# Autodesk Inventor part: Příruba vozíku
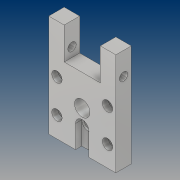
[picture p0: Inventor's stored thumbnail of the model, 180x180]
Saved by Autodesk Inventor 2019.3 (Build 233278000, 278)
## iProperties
Created: 2019-01
Part Number: Příruba vozíku
Material: Hliník 6061-AHC
Document SubType Name: Modeling
Designer: B-hon
Density: 2.7 g/cm^3
Appearance: Hliník – tmavý
Author: B-hon
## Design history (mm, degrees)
sketch "Náčrt1"
  geometry: L1 (-24.5, 16)-(24.5, 16); L2 (24.5, 16)-(24.5, -16); L3 (24.5, -16)-(-24.5, -16); L4 (-24.5, -16)-(-24.5, 16); L5 (-24.5, 16)-(24.5, -16); L6 (24.5, 16)-(-24.5, -16); L7 (32.5, -24)-(-32.5, -24); L8 (-32.5, -24)-(-32.5, 56); L9 (32.5, 56)-(32.5, -24); L10 (-32.5, 56)-(32.5, 56); 1 further point
  constraints: 20 end point, 3 horizontal, 3 parallel, 2 midpoint, 2 perpendicular
  dimensions: "d0" = 49 distance of L2.end L3.end; "d1" = 32 distance of L1.end L2.end; "d4" = 80 distance between parallel lines of L7 L10; "d21" = 8 distance between parallel lines of L9 L2; "d22" = 8 distance between parallel lines of L4 L8; "d23" = 8 distance between parallel lines of L7 L3
extrude "Vysunutí1" new body sketch "Náčrt1" distance "d5" = 12; taper "d6" = 0 deg
sketch "Náčrt2"
  geometry: L1 (0, 80)-(0, 0) reference; L2 (0, 0)-(-12, 0) reference; 2 further points
  dimensions: "d7" = 4.5 distance from line of L1 point (-4.5, 65); "d8" = 65 distance from line of L2 point (-4.5, 65)
hole "Díra1" sketch "Náčrt2" at (-4.5, 65) diameter "d9" = 8; stored, may be unused: countersink angle "d13" = 90 deg, drill point angle "d15" = 118 deg; dims "d10" = 6, "d11" = 4, "d12" = 2, "d14" = 8
sketch "Náčrt3"
  geometry: L1 (32.5, 56)-(-32.5, 56) reference; L2 (-17.5, 56)-(17.5, 56); L3 (17.5, 56)-(17.5, 32); L4 (17.5, 32)-(-17.5, 32); L5 (-17.5, 32)-(-17.5, 56); L6 (-32.5, -24)-(32.5, -24) reference; 1 further point
  constraints: 8 end point, 2 parallel, 1 horizontal, 1 perpendicular, 1 point on line
  dimensions: "d16" = 56 distance between parallel lines of L4 L6; "d17" = 35 distance of L3.end L4.end; "d18" = 15 distance from line of L1.end L5
extrude "Vysunutí2" cut sketch "Náčrt3" distance "d19" = 12; taper "d20" = 0 deg
sketch "Náčrt5"
  geometry: L1 (-24.5, 16)-(24.5, 16); L2 (24.5, 16)-(24.5, -16); L3 (24.5, -16)-(-24.5, -16); L4 (-24.5, -16)-(-24.5, 16); L5 (-24.5, 16)-(24.5, -16); L6 (24.5, 16)-(-24.5, -16); 5 further points
  constraints: 12 end point, 4 coincident, 2 midpoint, 2 parallel, 1 horizontal, 1 perpendicular
  dimensions: "d24" = 49 distance of L2.end L3.end; "d25" = 32 distance of L1.end L2.end
hole "Díra2" sketch "Náčrt5" at (-24.5, 16), (24.5, 16), (24.5, -16), (-24.5, -16) diameter "d26" = 5.3; stored, may be unused: countersink angle "d30" = 90 deg, drill point angle "d32" = 118 deg; dims "d27" = 6, "d28" = 10, "d29" = 5.7, "d31" = 8
node "Upravit přímo1"
sketch "Náčrt6"
  geometry: L1 (-32.5, -24)-(32.5, -24) reference; C1 r 6.5 at (0, -14); 1 further point
  constraints: 1 centre point
  dimensions: "d36" = 13 diameter of C1; "d37" = 10 distance from line of L1 C1.centre
extrude "Vysunutí3" cut sketch "Náčrt6" distance "d38" = 8; taper "d39" = 0 deg
sketch "Náčrt7"
  geometry: L1 (6.5, -48.468)-(-6.5, -48.468); L2 (-6.5, -48.468)-(-6.5, -14); L3 (-6.5, -14)-(6.5, -14); L4 (6.5, -14)-(6.5, -48.468); L5 (6.5, -48.468)-(-6.5, -14); L6 (-6.5, -48.468)-(6.5, -14); 3 further points
  constraints: 12 end point, 2 midpoint, 2 parallel, 1 horizontal, 1 horizontal alignment, 1 perpendicular, 1 other
  dimensions: "d40" = 13 distance of L2.end L3.end
extrude "Vysunutí4" cut sketch "Náčrt7" distance "d41" = 6; taper "d42" = 0 deg
node "Upravit přímo2"
sketch "Náčrt8"
  geometry: L1 (-32.5, -24)-(-6.5, -24) reference; L2 (-32.5, 63)-(-32.5, -24) reference; 2 further points
  dimensions: "d46" = 26 distance from line of L1 point (0, 2); "d47" = 32.5 distance from line of L2 point (0, 2)
hole "Díra3" sketch "Náčrt8" at (0, 2) diameter "d48" = 15; stored, may be unused: countersink angle "d52" = 90 deg, drill point angle "d54" = 118 deg; dims "d49" = 6, "d50" = 4, "d51" = 2, "d53" = 13
node "Upravit přímo3"
sketch "Náčrt11"
  geometry: L1 (0, 0)-(0, 15) reference; L2 (65, 0)-(0, 0) reference; 3 further points
  constraints: 1 horizontal alignment
  dimensions: "d76" = 52 distance of point (58.5, 7.5) point (6.5, 7.5); "d77" = 6.5 distance from line of L1 point (6.5, 7.5); "d78" = 7.5 distance from line of L2 point (6.5, 7.5)
hole "Díra6" sketch "Náčrt11" at (6.5, 7.5), (58.5, 7.5) diameter "d79" = 4.917; stored, may be unused: countersink angle "d83" = 90 deg, drill point angle "d85" = 0 deg; dims "d80" = 13, "d81" = 6, "d82" = 2, "d84" = 14.7
node "Těleso1"
feature "Posunout1" dims "d35" = 7
feature "Posunout2" dims "d45" = 3
feature "Posunout3" dims "d75" = 12
other parameters: "d33" = 0, "d34" = 0, "d43" = 0, "d44" = 0, "d73" = 0, "d74" = 0
